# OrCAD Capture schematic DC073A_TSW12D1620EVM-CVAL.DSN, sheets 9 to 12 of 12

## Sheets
9 PAGE09 - USB: size B
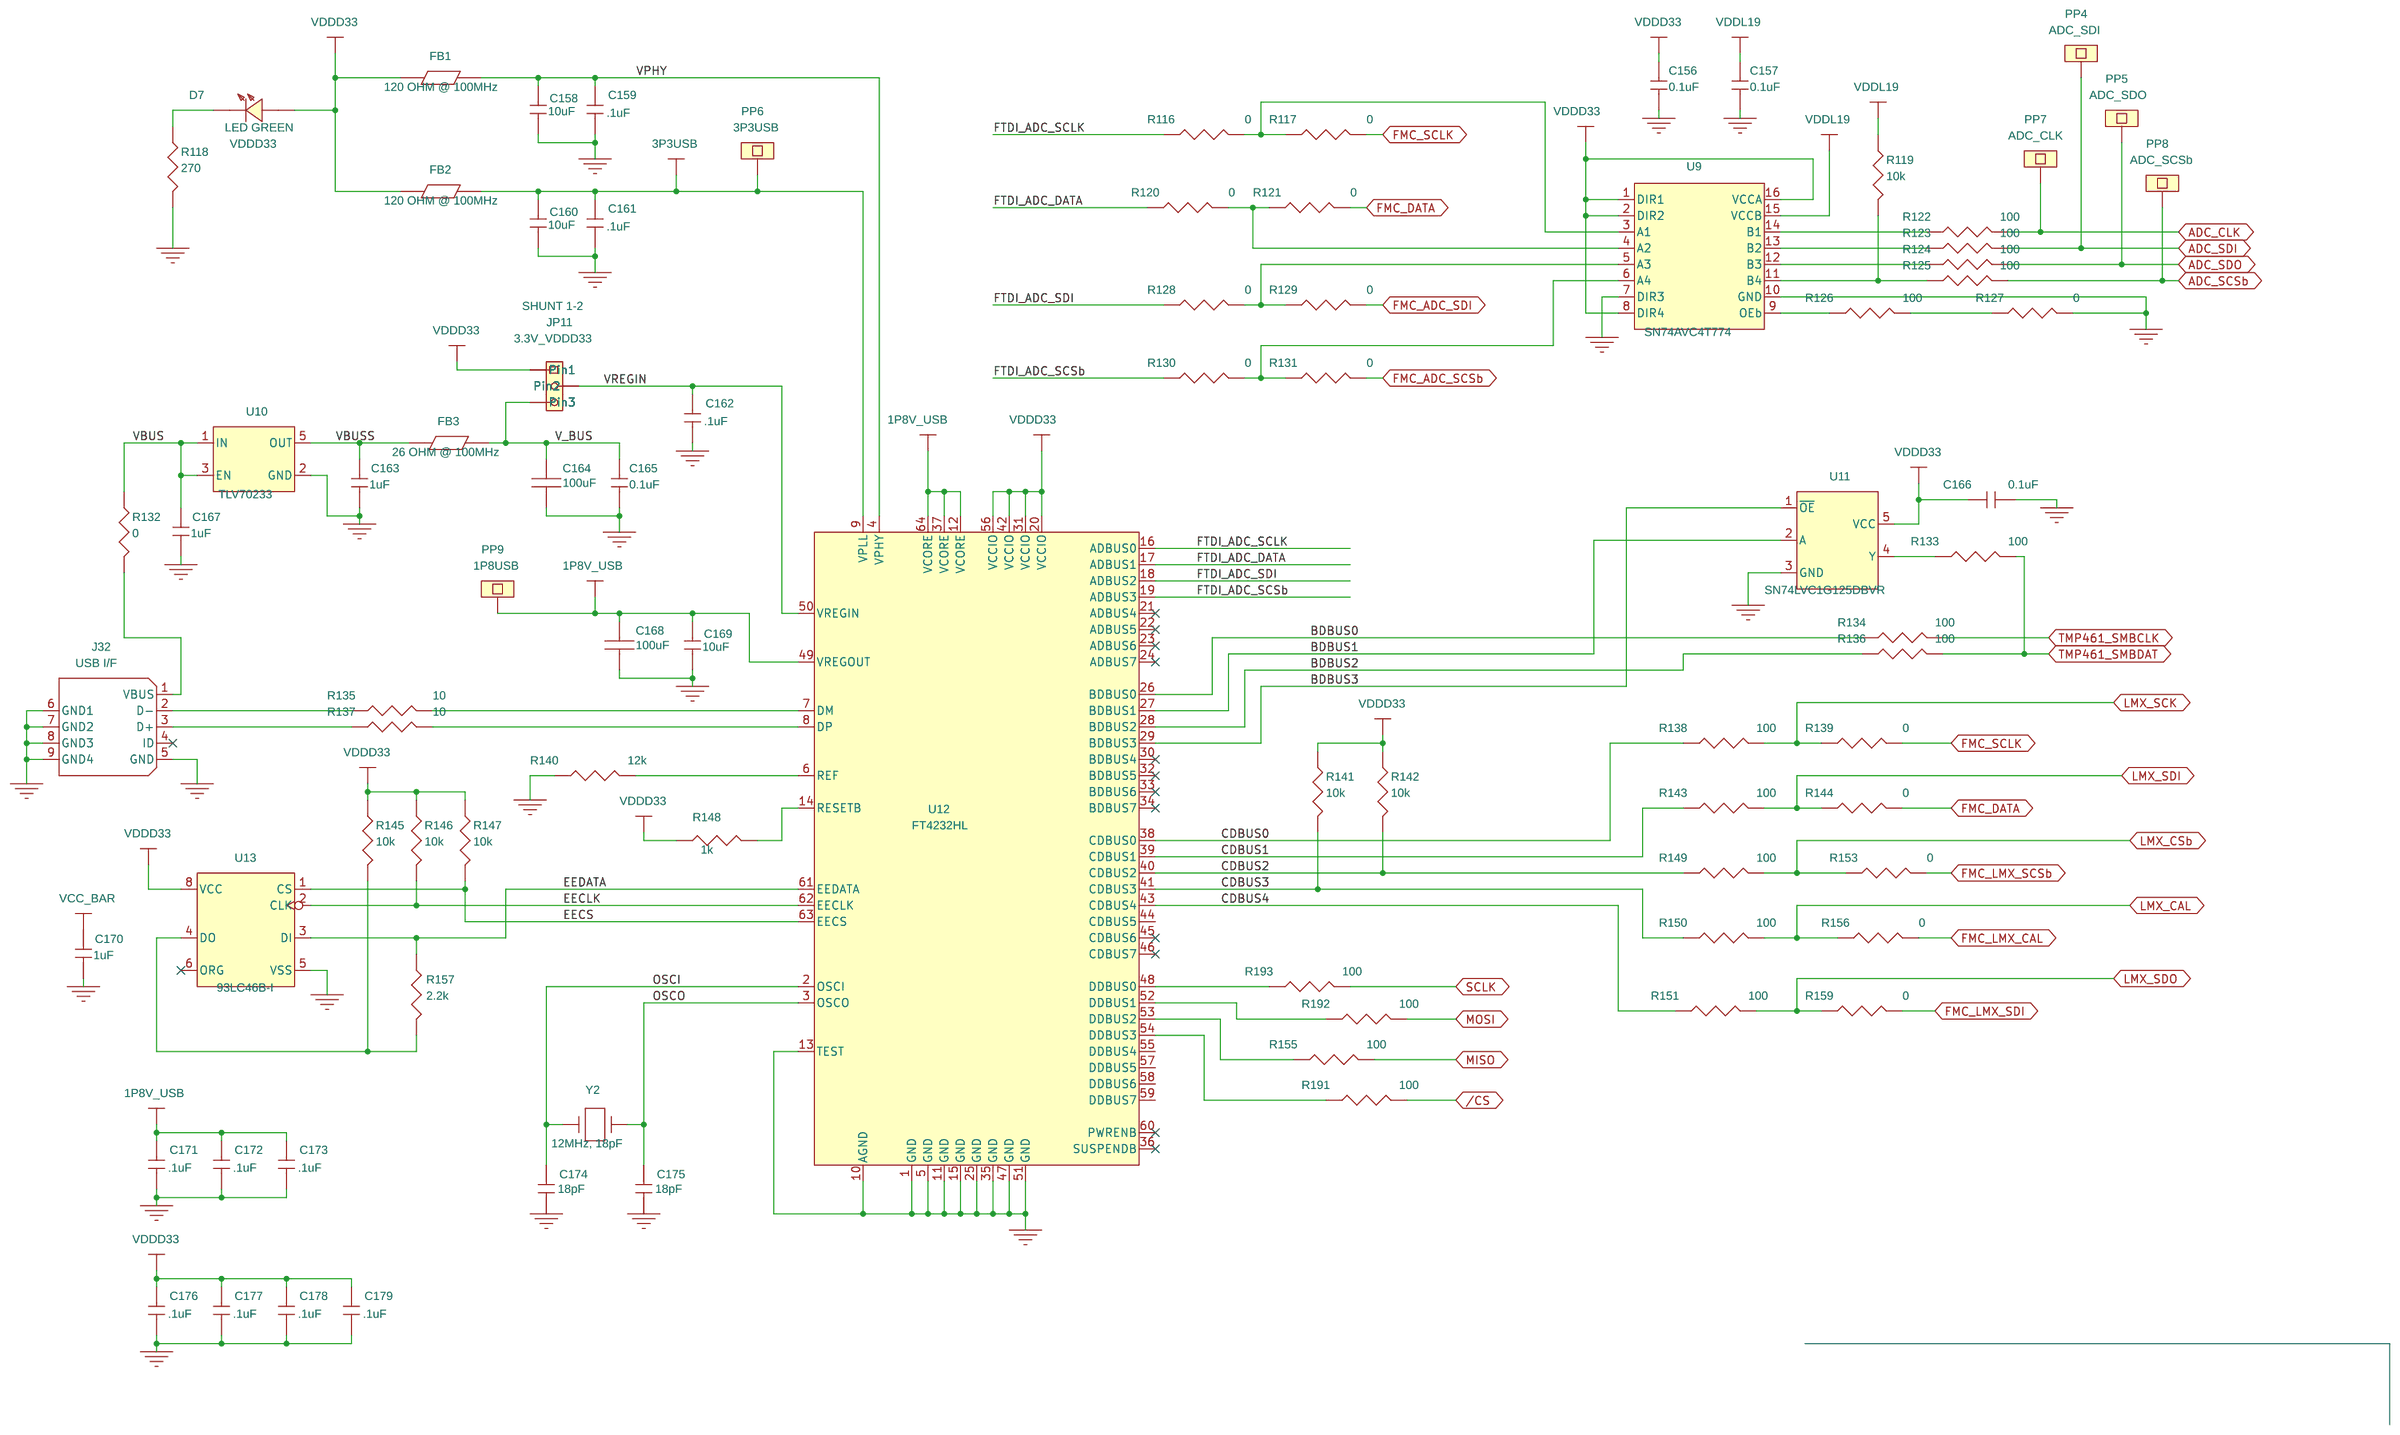
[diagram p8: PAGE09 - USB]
10 PAGE10 - POWER SUPPLIES: size B
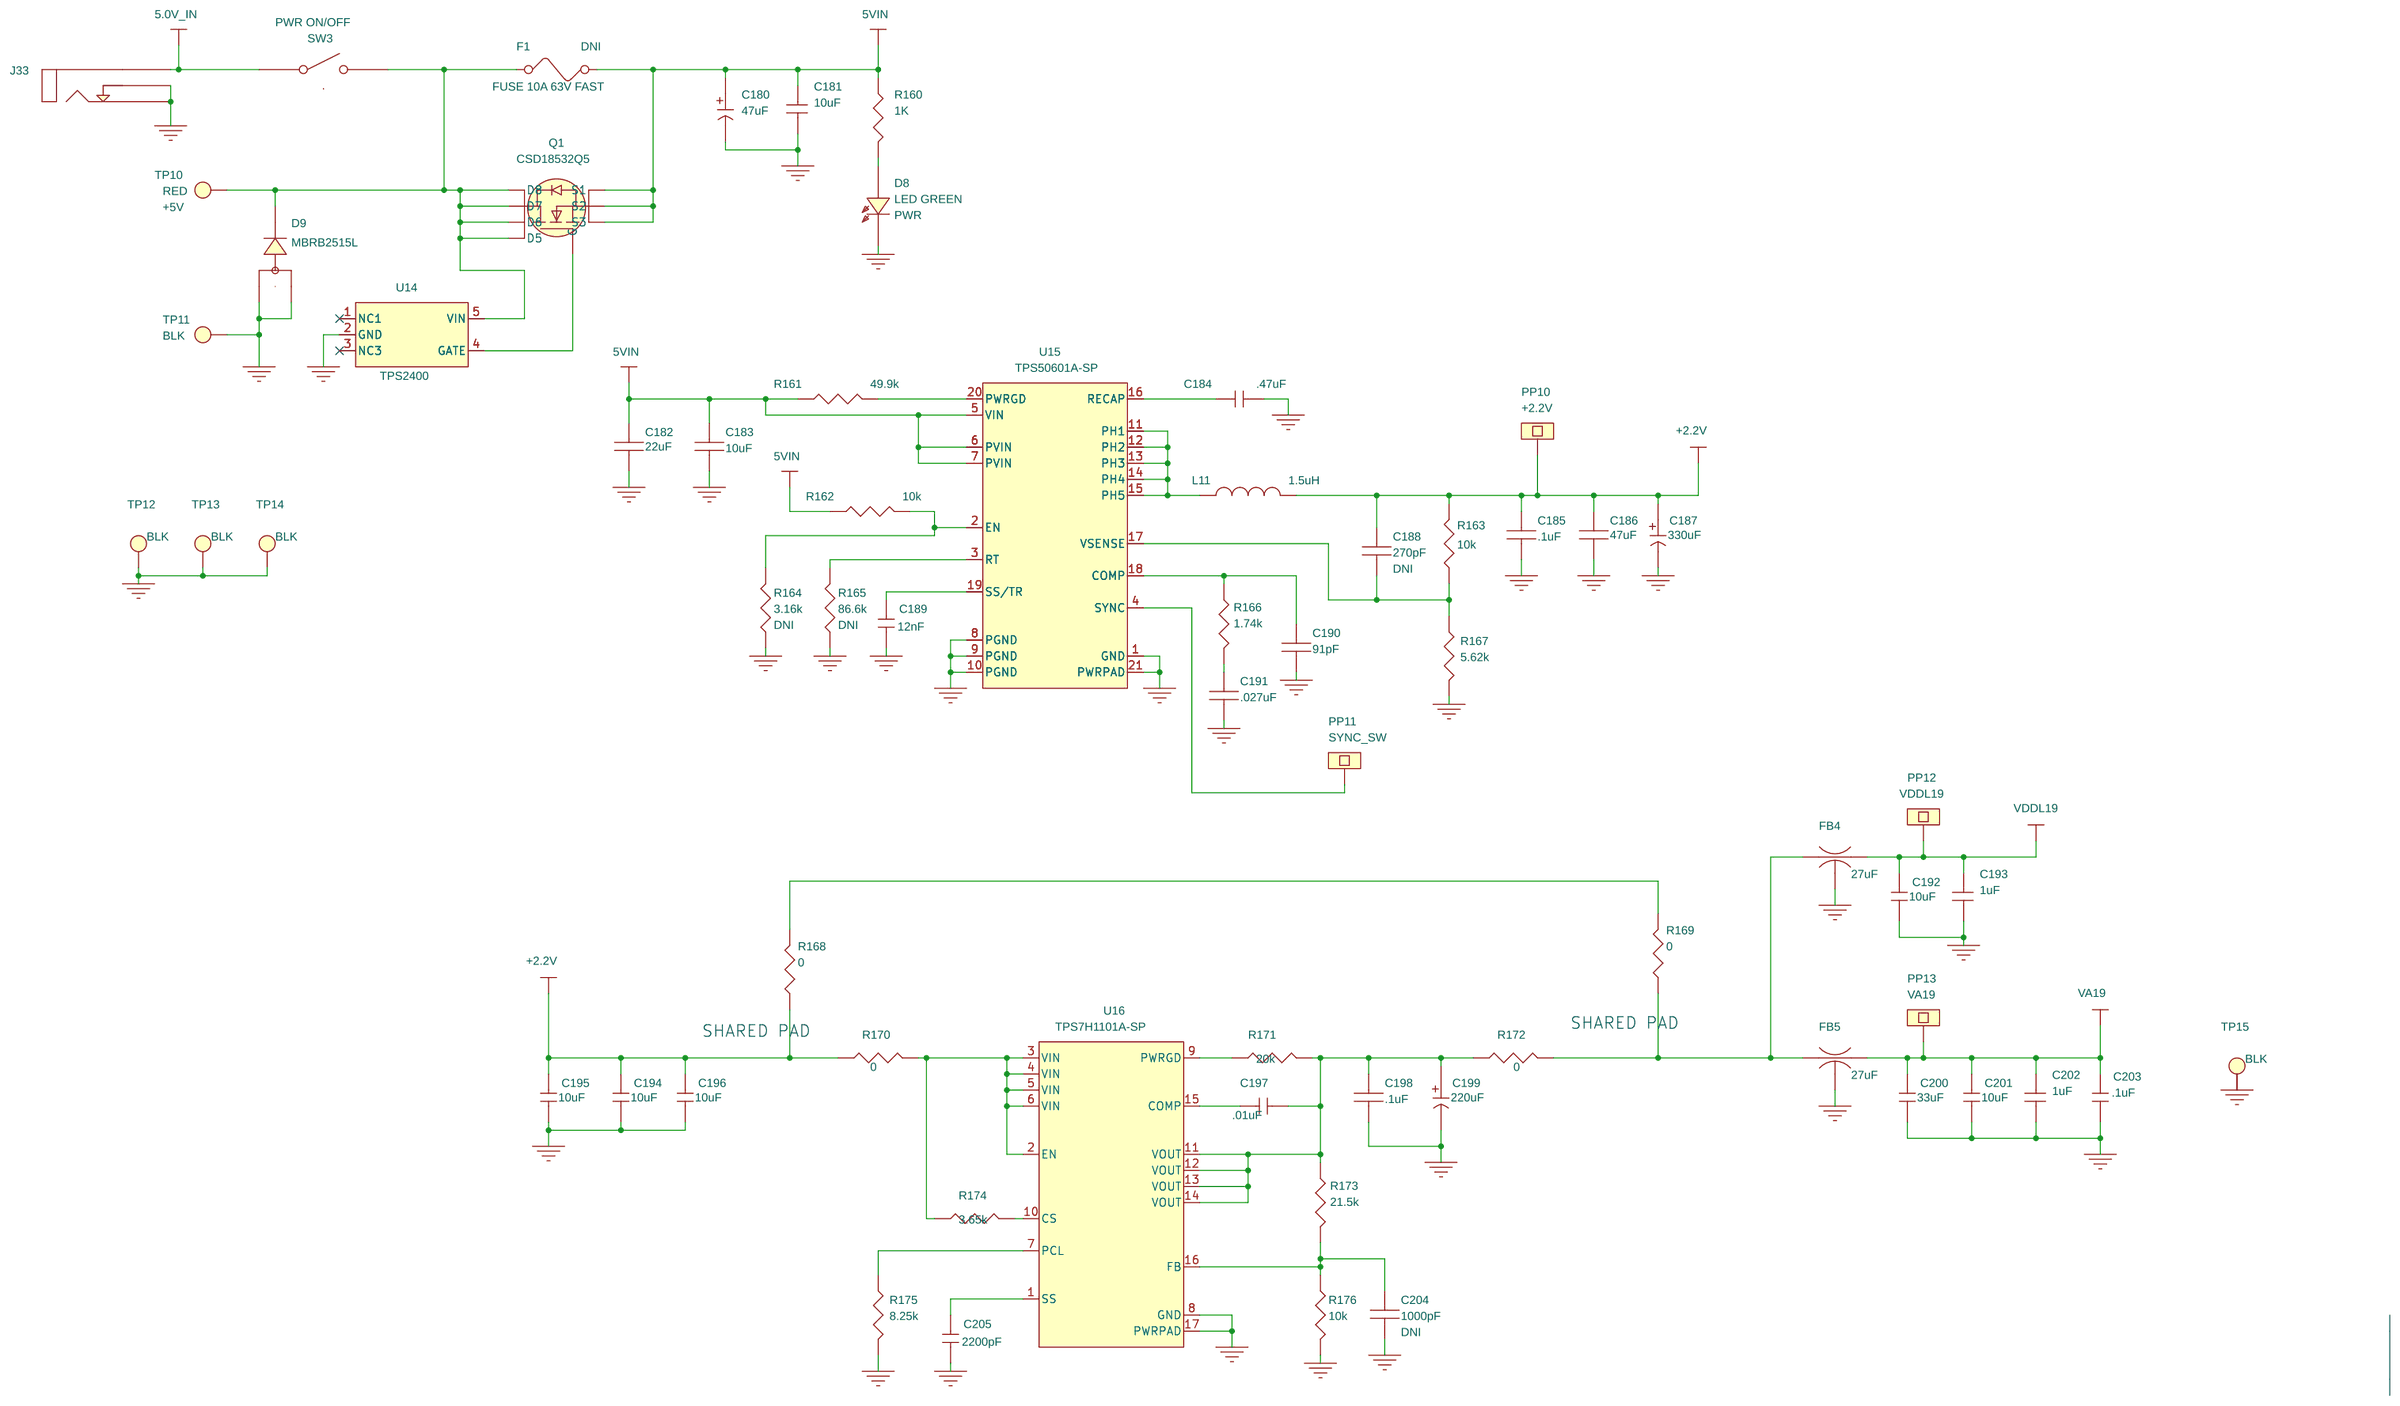
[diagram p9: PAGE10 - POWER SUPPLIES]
11 PAGE11 - POWER SUPPLIES: size B
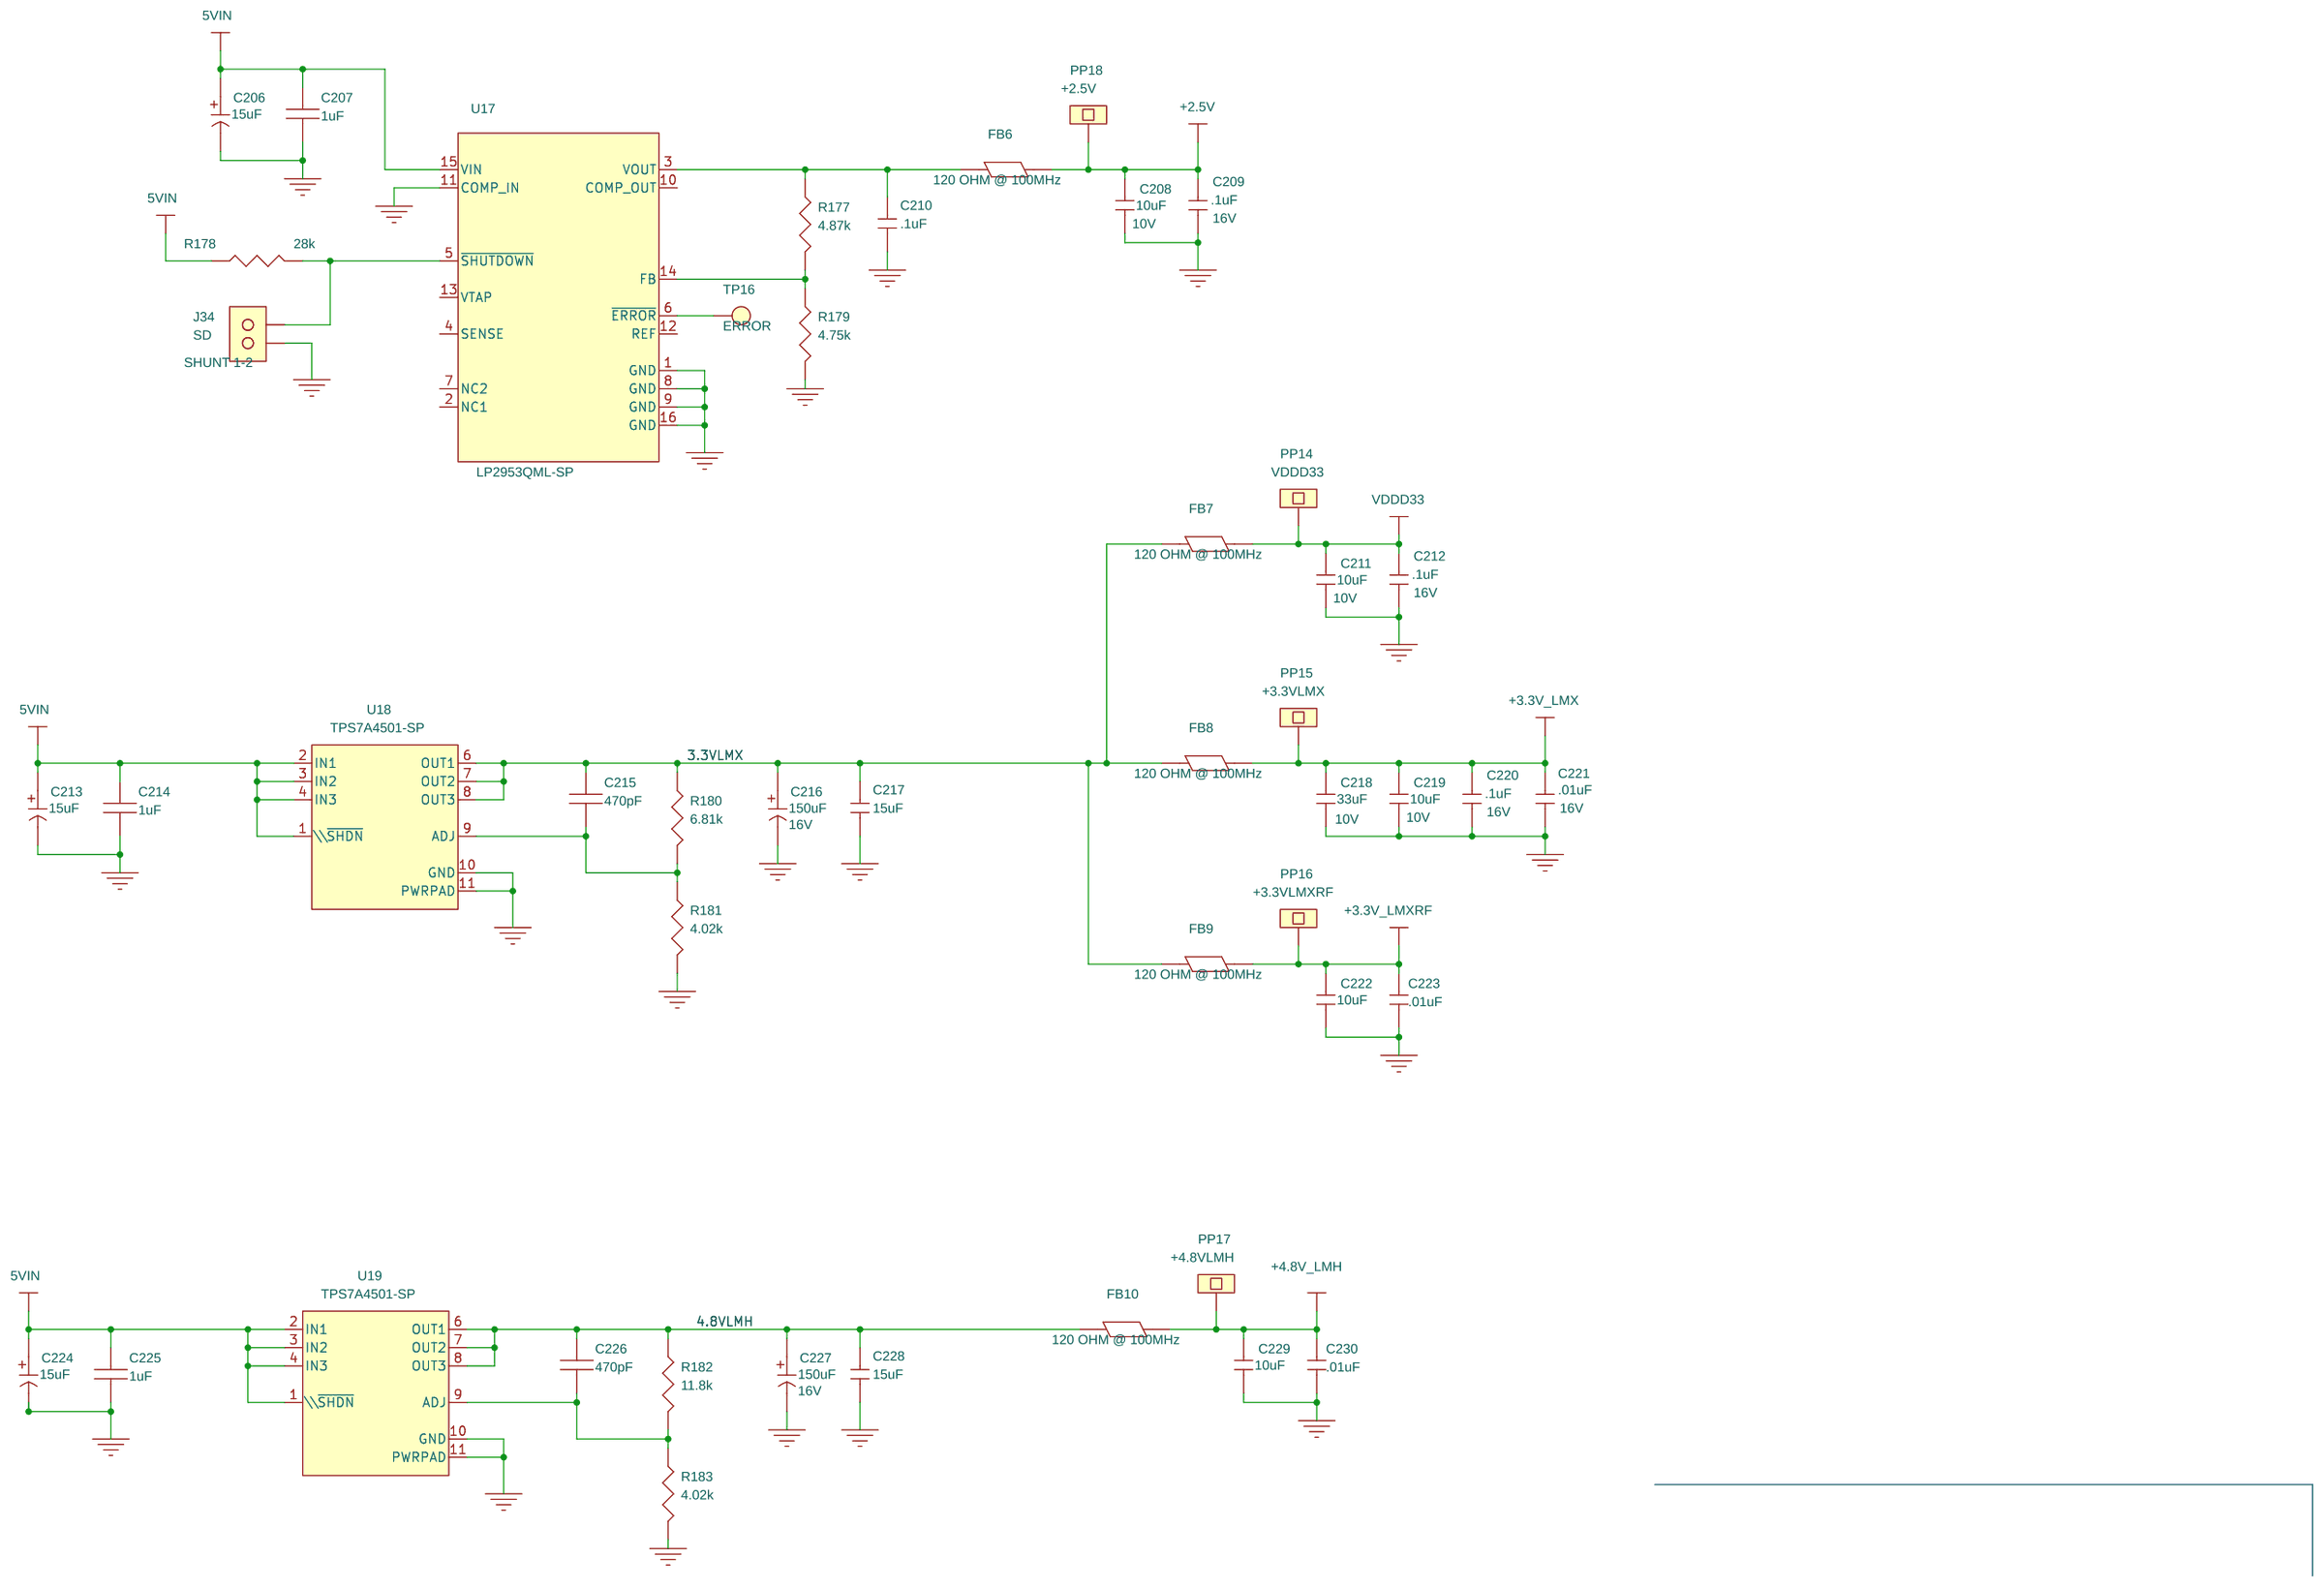
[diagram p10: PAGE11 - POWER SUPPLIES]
12 PAGE12 - MECHANICAL: size B
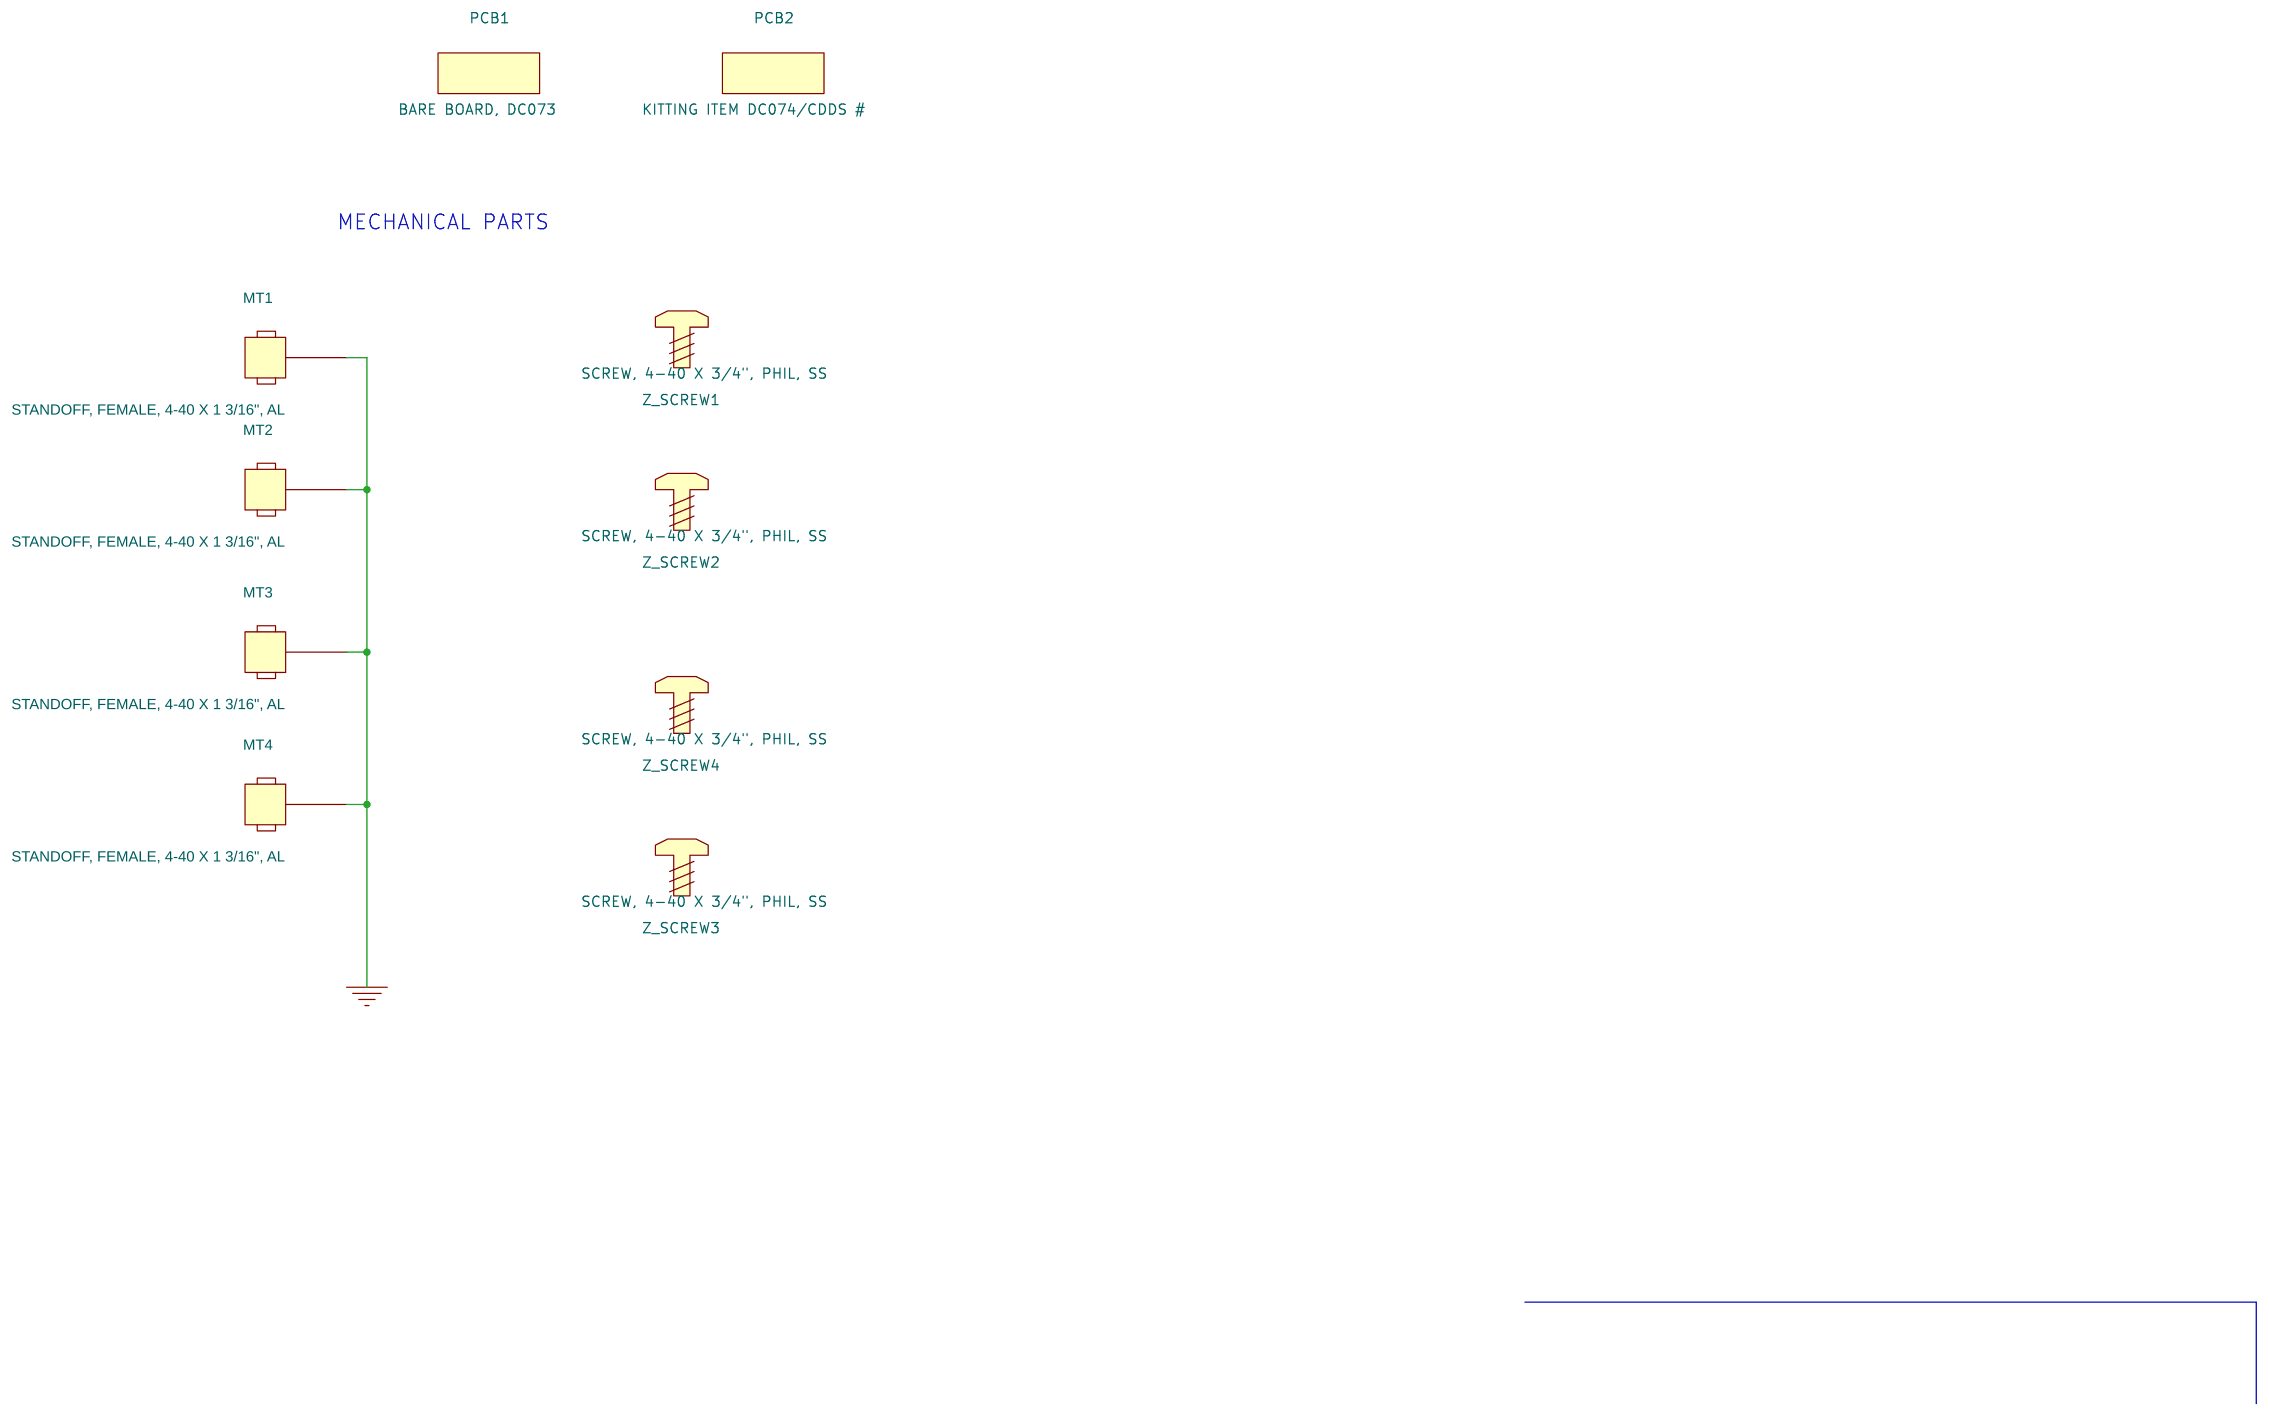
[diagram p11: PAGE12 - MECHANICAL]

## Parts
sheet PAGE09 - USB
C156  0.1uF  [0603]
C157  0.1uF  [0603]
C158  10uF  [0603]
C159  .1uF  [0201]
C160  10uF  [0603]
C161  .1uF  [0201]
C162  .1uF  [0201]
C163  1uF  [0603]
C164  100uF  [1206]
C165  0.1uF  [0603]
C166  0.1uF  [0603]
C167  1uF  [0603]
C168  100uF  [1206]
C169  10uF  [0603]
C170  1uF  [0603]
C171  .1uF  [0201]
C172  .1uF  [0201]
C173  .1uF  [0201]
C174  18pF  [0402]
C175  18pF  [0402]
C176  .1uF  [0201]
C177  .1uF  [0201]
C178  .1uF  [0201]
C179  .1uF  [0201]
D7  LED GREEN  [LED_0805]
FB1  120 OHM @ 100MHz  [IND_0603]
FB2  120 OHM @ 100MHz  [IND_0603]
FB3  26 OHM @ 100MHz  [IND_0603]
J32  CON, USB, MINI, AB, SMT  [CON_SMRT_USBMNE20_F]
JP11  HDR, THVT, 3POS, .100, GOLD  [HDR_THVT_1x3_100_M]
PP4  PROBE POINT  [PROBE_POINT_30PAD]
PP5  PROBE POINT  [PROBE_POINT_30PAD]
PP6  PROBE POINT  [PROBE_POINT_30PAD]
PP7  PROBE POINT  [PROBE_POINT_30PAD]
PP8  PROBE POINT  [PROBE_POINT_30PAD]
PP9  PROBE POINT  [PROBE_POINT_30PAD]
R116  0  [0402]
R117  0  [0402]
R118  270  [0402]
R119  10k  [0402]
R120  0  [0402]
R121  0  [0402]
R122  100  [0402]
R123  100  [0402]
R124  100  [0402]
R125  100  [0402]
R126  100  [0402]
R127  0  [0402]
R128  0  [0402]
R129  0  [0402]
R130  0  [0402]
R131  0  [0402]
R132  0  [0603]
R133  100  [0402]
R134  100  [0402]
R135  10  [0603]
R136  100  [0402]
R137  10  [0603]
R138  100  [0402]
R139  0  [0402]
R140  12k  [0603]
R141  10k  [0402]
R142  10k  [0402]
R143  100  [0402]
R144  0  [0402]
R145  10k  [0402]
R146  10k  [0402]
R147  10k  [0402]
R148  1k  [0603]
R149  100  [0402]
R150  100  [0402]
R151  100  [0402]
R153  0  [0402]
R155  100  [0402]
R156  0  [0402]
R157  2.2k  [0402]
R159  0  [0402]
R191  100  [0402]
R192  100  [0402]
R193  100  [0402]
U9  SN74AVC4T774  [TSSOP_16_201x177_26]
U10  TLV70233  [SOT_5_120x69_37]
U11  SN74LVC1G125DBVR  [SOT_5_120x69_57]
U12  FT4232HL  [LQFP_64_402x402_20]
U13  93LC46B-I  [MSOP_8_118x118_0p65MM]
Y2  12MHz, 18pF  [XTAL_2_SM_126x197]
Z_SH-H1  SHUNT- HEADER
sheet PAGE10 - POWER SUPPLIES
C180  47uF  [TANT_B]
C181  10uF  [0603]
C182  22uF  [1206]
C183  10uF  [0805]
C184  .47uF  [0402]
C185  .1uF  [0805]
C186  47uF  [1206]
C187  330uF  [TANT_D]
C188  270pF  [0603]
C189  12nF  [0402]
C190  91pF  [0805]
C191  .027uF  [0805]
C192  10uF  [0603]
C193  1uF  [0402]
C194  10uF  [0603]
C195  10uF  [0603]
C196  10uF  [0603]
C197  .01uF  [0201]
C198  .1uF  [0805]
C199  220uF  [TANT_D]
C200  33uF  [0805]
C201  10uF  [0603]
C202  1uF  [0402]
C203  .1uF  [0402]
C204  1000pF  [0805]
C205  2200pF  [0201]
D8  LED GREEN  [LED_0805]
D9  MBRB2515L  [DIODE_MBRB2515L]
F1  FUSE 10A 63V FAST  [1206]
FB4  27uF  [1206_BEAD_NFM31P]
FB5  27uF  [1206_BEAD_NFM31P]
J33  CONN, JACK, PWR, MINI, R/A, TH  [CON_RAPC722_JACK_THVT_3]
L11  1.5uH  [IND_SM_6p7MMx6p7MM]
PP10  PROBE POINT  [PROBE_POINT_30PAD]
PP11  PROBE POINT  [PROBE_POINT_30PAD]
PP12  PROBE POINT  [PROBE_POINT_30PAD]
PP13  PROBE POINT  [PROBE_POINT_30PAD]
Q1  CSD18532Q5  [SON_Q5B_8]
R160  1K  [0402]
R161  49.9k  [0402]
R162  10k  [0402]
R163  10k  [0603]
R164  3.16k  [0402]
R165  86.6k  [0402]
R166  1.74k  [0402]
R167  5.62k  [0603]
R168  0  [0805]
R169  0  [0805]
R170  0  [0805]
R171  20k  [0402]
R172  0  [0805]
R173  21.5k  [0402]
R174  3.65k  [0402]
R175  8.25k  [0402]
R176  10k  [0402]
SW3  PWR ON/OFF  [SW_SMVT_SPST_ES02]
TP10  RED  [TP_THVT_125_RND_063D]
TP11  BLK  [TP_THVT_125_RND_063D]
TP12  BLK  [TP_THVT_100_RND]
TP13  BLK  [TP_THVT_100_RND]
TP14  BLK  [TP_THVT_100_RND]
TP15  BLK  [TP_THVT_100_RND]
U14  TPS2400  [DBV5]
U15  TPS50601A-SP  [CFP_20_300x510_50_PWRPAD]
U16  TPS7H1101A-SP  [DUAL_FLATPACK_TPS7H1101-SP]
sheet PAGE11 - POWER SUPPLIES
C206  15uF  [TANT_X]
C207  1uF  [0805]
C208  10uF  [0603]
C209  .1uF  [0402]
C210  .1uF  [1210]
C211  10uF  [0603]
C212  .1uF  [0402]
C213  15uF  [TANT_X]
C214  1uF  [0805]
C215  470pF  [0805]
C216  150uF  [7343]
C217  15uF  [0805]
C218  33uF  [0805]
C219  10uF  [0603]
C220  .1uF  [0402]
C221  .01uF  [0201]
C222  10uF  [0603]
C223  .01uF  [0201]
C224  15uF  [TANT_X]
C225  1uF  [0805]
C226  470pF  [0805]
C227  150uF  [7343]
C228  15uF  [0805]
C229  10uF  [0603]
C230  .01uF  [0201]
FB6  120 OHM @ 100MHz  [1206]
FB7  120 OHM @ 100MHz  [1206]
FB8  120 OHM @ 100MHz  [1206]
FB9  120 OHM @ 100MHz  [1206]
FB10  120 OHM @ 100MHz  [1206]
J34  HDR, THVT, 2POS, .100, GOLD  [HDR_THVT_1x2_100_M]
PP14  PROBE POINT  [PROBE_POINT_30PAD]
PP15  PROBE POINT  [PROBE_POINT_30PAD]
PP16  PROBE POINT  [PROBE_POINT_30PAD]
PP17  PROBE POINT  [PROBE_POINT_30PAD]
PP18  PROBE POINT  [PROBE_POINT_30PAD]
R177  4.87k  [0805]
R178  28k  [0402]
R179  4.75k  [0805]
R180  6.81k  [0805]
R181  4.02k  [0805]
R182  11.8k  [0805]
R183  4.02k  [0805]
SHN12  SHUNT HEADER
TP16  ORN  [TP_THVT_100_RND]
U17  LP2953QML-SP  [CFP_NAC_16_0P5mm]
U18  TPS7A4501-SP  [CFP_10_270x276_50_PWRPAD]
U19  TPS7A4501-SP  [CFP_10_270x276_50_PWRPAD]
sheet PAGE12 - MECHANICAL
MT1  STANDOFF, FEMALE, 4-40 X 1 3/16", AL  [MFG125_PLATED]
MT2  STANDOFF, FEMALE, 4-40 X 1 3/16", AL  [MFG125_PLATED]
MT3  STANDOFF, FEMALE, 4-40 X 1 3/16", AL  [MFG125_PLATED]
MT4  STANDOFF, FEMALE, 4-40 X 1 3/16", AL  [MFG125_PLATED]
PCB1  BARE BOARD, DC073
PCB2  KITTING ITEM DC074/CDDS #
Z_SCREW1  SCREW, 4-40 X 3/4", PHIL, SS
Z_SCREW2  SCREW, 4-40 X 3/4", PHIL, SS
Z_SCREW3  SCREW, 4-40 X 3/4", PHIL, SS
Z_SCREW4  SCREW, 4-40 X 3/4", PHIL, SS

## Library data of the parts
C156 C157 C165 C166 = CAP_0603_0.1uF
C158 C160 C169 = CAP_0603_10uF: CLASS: DISCRETE
C159 C161 C162 C171-C173 C176-C179 = CAP_0201_0.1uF: Mfr_Name: MURATA; Mfr_Part_Number: GRM033R61A104KE15D
C163 C167 C170 = CAP_0603_1uF
C164 C168 = CAP_1206_100uF_6.3V
C174 C175 = CAP_0402_18pF
D7 = LED_GREEN_0: TI_SILKTEXT: VDDD33
FB1 FB2 = FERRITE_BEAD_0603_120_H
FB3 = FERRITE_BEAD_0603_26_H
J32 = USB_MINI_AB_MNE20-5G5P10: Mfr_Name: WURTH ELEKTRONIK; Mfr_Part_Number: 651305142821; TI_SILKTEXT: USB I/F
JP11 = JUMPER_1X3_100: Mfr_Part_Number: HTSW-103-07-G-S; Note: SHUNT 1-2; TI_Silktext: 3.3V_VDDD33
PP4 = PROBE_POINT_0: Mfr_Name: HARWIN; Mfr_Part_Number: P1113SS3; TI_Silktext: ADC_SDI
PP5 = PROBE_POINT_0: Mfr_Name: HARWIN; Mfr_Part_Number: P1113SS3; TI_Silktext: ADC_SDO
PP6 = PROBE_POINT_0: Mfr_Name: HARWIN; Mfr_Part_Number: P1113SS3; TI_Silktext: 3P3USB
PP7 = PROBE_POINT_0: Mfr_Name: HARWIN; Mfr_Part_Number: P1113SS3; TI_Silktext: ADC_CLK
PP8 = PROBE_POINT_0: Mfr_Name: HARWIN; Mfr_Part_Number: P1113SS3; TI_Silktext: ADC_SCSb
PP9 = PROBE_POINT_0: Mfr_Name: HARWIN; Mfr_Part_Number: P1113SS3; TI_Silktext: 1P8USB
R116 R120 R127 R128 R130 = Res_0402_Zero_H
R117 R121 R129 R131 R139 R144 R153 R156 R159 = Res_0402_Zero_H_DNI: Mfr_Part_Number: ERJ-2GE0R00X
R118 = Res_0402_270
R119 R141 R142 R145-R147 R176 = Res_0402_10k
R122-R126 R133 R134 R136 R138 R143 R149-R151 R155 R191-R193 = Res_0603_100_H: Mfr_Part_Number: ERJ-2RKF1000X
R132 = Res_0603_Zero
R135 R137 = Res_0603_10
R140 = Res_0603_12k
R148 = Res_0603_1k_H
R157 = Res_0603_2.2k: Mfr_Part_Number: ERJ-2RKF2201X
U9 = SN74AVC4T774: Mfr_Name: Texas Instruments
U10 = TLV702: Mfr_Part_Number: TLV70233DBVT
U11 = SN74LVC1G125DBVR: Mfr_Name: Texas Instruments
U12 = FT4232HL: Mfr_Part_Number: FT4232HL-REEL
U13 = EEPROM_93LC46B: Mfr_Part_Number: 93LC46B-I/MS
Y2 = CRYSTAL_ABM3_0
Z_SH-H1 = SHUNT-HEADER_-_3POS: Mfr_Part_Number: 1-382811-6
C180 = CAP_POL-B_0: Mfr_Name: AVX; Mfr_Part_Number: TPSB476K010R0250; TOL: 10%
C181 = CAP_NP_1: Mfr_Name: TDK; Mfr_Part_Number: C1608X5R1A106K080AC; TOL: 10%; VOLTAGE: 10V
C182 = CAP_1206_2.2uF: Mfr_Part_Number: GRM31CR61A226ME19L
C183 = CAP_0805_10uF_10V: Mfr_Part_Number: GCJ21BR71A106KE01L
C184 = CAP_0805_0.1uF_X7R_50V: Mfr_Name: Taiyo Yuden; Mfr_Part_Number: LMK105BJ474KV-F
C185 C198 = CAP_0805_.1uF_25V
C186 = CAP_1206_47uF: Mfr_Part_Number: GRM31CE70G476ME15L
C187 = CAP_TANT_D_220uF_6.3V: Mfr_Name: KEMET; Mfr_Part_Number: T491D337K006AT; Tol: 10%
C188 = CAP_0805_9.0pF: Mfr_Name: Murata; Mfr_Part_Number: GCM1885C2A271FA16D; Note: DNI
C189 = CAP_0201_0.1uF: Mfr_Name: MURATA; Mfr_Part_Number: GRM155R71C123JA01D
C190 = CAP_0805_91pF_50V
C191 = CAP_0805_.027uF_50V
C192 C194-C196 C201 = CAP0201_0: Mfr_Name: TDK; Mfr_Part_Number: C1608X5R1A106K080AC; TOL: 20%; VOLTAGE: 10V
C193 C202 = CAP_NP_1: Mfr_Name: YAGEO; Mfr_Part_Number: CC0402MRX5R6BB105; TOL: 20%; VOLTAGE: 6.3V
C197 = CAP_0201_10000pF
C199 = CAP_TANT_D_220uF_6.3V
C200 C218 = CAP0201_0: Mfr_Name: TDK; Mfr_Part_Number: C2012X5R1A336M125AC; TOL: 20%; VOLTAGE: 10V
C203 C209 C212 C220 = CAP0603: Mfr_Name: MURATA; Mfr_Part_Number: GRM155R71C104KA88D; TOL: 10%; Voltage: 16V
C204 = CAP_0805_1000pF_25V: Mfr_Part_Number: GRM216R71E102KA01D; Note: DNI
C205 = CAP_0201_2200pF
D8 = LED_GREEN_0: Mfr_Part_Number: LTST-C170KGKT; TI_SILKTEXT: PWR
D9 = DIODE_MBRB2515L
F1 = FUSE_0: Mfr_Name: TE Connectivity; Mfr_Part_Number: 1206SFF200F/63-2; Note: DNI
FB4 FB5 = BEAD_NFM31P: Mfr_Name: Murata; Mfr_Part_Number: NFM31PC276B0J3L; Tolerance: 20%
J33 = CONN_JACK_PWR: Mfr_Name: SWITCHCRAFT; Mfr_Part_Number: RAPC722X
L11 = IND_POWER_1.5uH
PP10 = PROBE_POINT_0: Mfr_Name: HARWIN; Mfr_Part_Number: P1113SS3; TI_Silktext: +2.2V
PP11 = PROBE_POINT_0: Mfr_Name: HARWIN; Mfr_Part_Number: P1113SS3; TI_Silktext: SYNC_SW
PP12 = PROBE_POINT_0: Mfr_Name: HARWIN; Mfr_Part_Number: P1113SS3; TI_Silktext: VDDL19
PP13 = PROBE_POINT_0: Mfr_Name: HARWIN; Mfr_Part_Number: P1113SS3; TI_Silktext: VA19
Q1 = CSD18532Q5B: Mfr_Name: Texas Instruments
R160 = Res_0402_1k: TOL: 1%
R161 = Res_0402_49.9k: Mfr_Part_Number: ERJ-2RKF4992X
R162 = Res_0402_28k_H: Mfr_Part_Number: ERJ-2RKF1002X
R163 = Res_0402_10k_H: Mfr_Part_Number: ERJ-3EKF1002V
R164 = Res_0402_9.31k_H: Mfr_Part_Number: ERJ-2RKF3161X; Note: DNI
R165 = Res_0402_86.6k_H: Mfr_Part_Number: ERJ-2RKF8662X; Note: DNI
R166 = Res_0402_1.82k: Mfr_Part_Number: ERJ-2RKF1741X
R167 = Res_0805_4.87k: ALTERNATE_PART_NUMBER: 7.15k, ERJ-6ENF7151V; Mfr_Name: PANASONIC; Mfr_Part_Number: ERJ-3EKF5621V
R168-R170 R172 = Res_0402_Zero_H_DNI: Mfr_Name: Keystone; Mfr_Part_Number: 5106
R171 = Res_0402_20K_H
R173 = Res_0402_21.5k
R174 = Res_0402_3.65K_H
R175 = Res_0402_8.25: Mfr_Part_Number: CRCW04028K25FKED
SW3 = SW_KEY-SPST_1: Mfr_Name: C&K; Mfr_Part_Number: ES02MSABE
TP10 = TESTLOOP_BLACK: Mfr_Name: KEYSTONE; Mfr_Part_Number: 5010; TI_SILKTEXT: +5V
TP11 = TESTPOINT_BLK: Mfr_Name: KEYSTONE; Mfr_Part_Number: 5011
TP12-TP15 = TESTPOINT_BLK: Mfr_Name: KEYSTONE; Mfr_Part_Number: 5001
U14 = TPS2400: Mfr_Name: Texas Instruments; Mfr_Part_Number: TPS2400DBVT
U15 = TPS50601A-SP_0
U16 = TPS7H1101-SP: Mfr_Part_Number: TPS7H1101AHKR/EM
C206 C213 C224 = CAP_TANT_X_15uF_50V
C207 C214 C225 = CAP_0805_1uF_50V
C208 C211 C219 C222 C229 = CAP0201_0: Mfr_Name: TDK; Mfr_Part_Number: C1608X5R1A106K080AC; TOL: 10%; VOLTAGE: 10V
C210 = CAP_1210_.1uF_50V
C215 C226 = CAP_0805_470pF
C216 C227 = CAP_TANT_X_15uF_50V: Mfr_Name: AVX; Mfr_Part_Number: TPME157K016R0030; Tol: 10%; Voltage: 16V
C217 C228 = CAP_1210_.1uF_50V: Mfr_Name: TDK; Mfr_Part_Number: C2012X5R1C156M125AC
C221 C223 C230 = CAP0402_0: Mfr_Name: YAGEO; Mfr_Part_Number: CC0201KRX7R7BB103; TOL: 10%; Voltage: 16V
FB6-FB10 = FERRITE_BEAD_0402_H: Isat: 500mA; Mfr_Name: MURATA; Mfr_Part_Number: BLM31PG121SN1L
J34 = HEADER_1x2_0: Mfr_Part_Number: HTSW-102-07-G-S; Note: SHUNT 1-2; TI_SILKTEXT: SD
PP14 = PROBE_POINT_0: Mfr_Name: HARWIN; Mfr_Part_Number: P1113SS3; TI_Silktext: VDDD33
PP15 = PROBE_POINT_0: Mfr_Name: HARWIN; Mfr_Part_Number: P1113SS3; TI_Silktext: +3.3VLMX
PP16 = PROBE_POINT_0: Mfr_Name: HARWIN; Mfr_Part_Number: P1113SS3; TI_Silktext: +3.3VLMXRF
PP17 = PROBE_POINT_0: Mfr_Name: HARWIN; Mfr_Part_Number: P1113SS3; TI_Silktext: +4.8VLMH
PP18 = PROBE_POINT_0: Mfr_Name: HARWIN; Mfr_Part_Number: P1113SS3; TI_Silktext: +2.5V
R177 = Res_0805_6.81k: Mfr_Part_Number: ERJ-6ENF4871V
R178 = Res_0402_28k_H
R179 = Res_0805_4.02k: Mfr_Part_Number: ERJ-6ENF4751V
R180 = Res_0805_6.81k
R181 R183 = Res_0805_4.02k
R182 = Res_0805_6.81k: Mfr_Part_Number: ERJ-6ENF1182V
SHN12 = SHUNT_HEADER: Mfr_Name: Sullins; Mfr_Part_Number: SPC02SYAN
TP16 = TESTPOINT_ORANGE: TI_SILKTEXT: ERROR
U17 = LP2953QML-SP
U18 U19 = TPS7A4501-SP
MT1-MT4 = MOUNTING_HOLE: Mfr_Name: RAF; Mfr_Part_Number: 1648-440-AL
PCB1 = BARE_BOARD: Mfr_Name: ANY VENDOR; Mfr_Part_Number: TSW12D1620EVM-CVAL REV A
PCB2 = BARE_BOARD: Mfr_Name: ANY VENDOR; Mfr_Part_Number: DC074 REV A
Z_SCREW1-Z_SCREW4 = STANDOFF-SCREW: Mfr_Part_Number: PMSSS 440 0075 PH; Note: SCREW FOR STANDOFF

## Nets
3.3VLMX: C215.1 C216.1 C217.1 FB7.1 FB8.1 FB9.1 R180.1 U18.6(OUT1) U18.7(OUT2) U18.8(OUT3)
4.8VLMH: C226.1 C227.1 C228.1 FB10.1 R182.1 U19.6(OUT1) U19.7(OUT2) U19.8(OUT3)
5.0V_IN: J33.1 SW3.1
5VIN: C180.1 C181.1 C182.1 C183.1 C206.1 C207.1 C213.1 C214.1 C224.1 C225.1 F1.2 Q1.1(S1) Q1.2(S2) Q1.3(S3) R160.1 R161.1 R162.1 R178.1 U15.5(VIN) U15.6(PVIN) U15.7(PVIN) U17.15(VIN) U18.1(\\~{SHDN}) U18.2(IN1) U18.3(IN2) U18.4(IN3) U19.1(\\~{SHDN}) U19.2(IN1) U19.3(IN2) U19.4(IN3)
+2.2V: C185.1 C186.1 C187.1 C188.1 C194.1 C195.1 C196.1 L11.2 PP10.1 R163.2 R168.1 R170.1
+2.5V: C208.1 C209.1 FB6.2 PP18.1 ; also on sheet 5
+3.3V_LMX: C218.1 C219.1 C220.1 C221.1 FB8.2 PP15.1 ; also on sheet 7
+3.3V_LMXRF: C222.1 C223.1 FB9.2 PP16.1 ; also on sheet 7
+4.8V_LMH: C229.1 C230.1 FB10.2 PP17.1 ; also on sheet 3
GND: C156.2 C157.2 C158.2 C159.2 C160.2 C161.2 C162.2 C163.2 C164.2 C165.2 C166.2 C167.2 C168.2 C169.2 C170.2 C171.2 C172.2 C173.2 C174.2 C175.2 C176.2 C177.2 C178.2 C179.2 C180.2 C181.2 C182.2 C183.2 C184.2 C185.2 C186.2 C187.2 C189.2 C190.2 C191.2 C192.2 C193.2 C194.2 C195.2 C196.2 C198.2 C199.2 C200.2 C201.2 C202.2 C203.2 C204.2 C205.2 C206.2 C207.2 C208.2 C209.2 C210.2 C211.2 C212.2 C213.2 C214.2 C216.2 C217.2 C218.2 C219.2 C220.2 C221.2 C222.2 C223.2 C224.2 C225.2 C227.2 C228.2 C229.2 C230.2 D8.2(CATHODE) D9.1 D9.3 FB4.2 FB5.2 J32.5(GND) J32.6(GND1) J32.7(GND2) J32.8(GND3) J32.9(GND4) J33.2 J33.3 J34.2 MT1.1 MT2.1 MT3.1 MT4.1 R118.2 R127.2 R140.1 R164.1 R165.1 R167.2 R175.2 R176.2 R179.2 R181.2 R183.2 TP11.1(TP) TP12.1(TP) TP13.1(TP) TP14.1(TP) TP15.1(TP) U9.7(DIR3) U9.10(GND) U10.2(GND) U11.3(GND) U12.1(GND) U12.5(GND) U12.10(AGND) U12.11(GND) U12.13(TEST) U12.15(GND) U12.25(GND) U12.35(GND) U12.47(GND) U12.51(GND) U13.5(VSS) U14.2(GND) U15.1(GND) U15.8(PGND) U15.9(PGND) U15.10(PGND) U15.21(PWRPAD) U16.8(GND) U16.17(PWRPAD) U17.1(GND) U17.8(GND) U17.9(GND) U17.11(COMP_IN) U17.16(GND) U18.10(GND) U18.11(PWRPAD) U19.10(GND) U19.11(PWRPAD) ; also on sheet 1 3 4 5 6 7 8
VBUS: C167.1 R132.1 U10.1(IN) U10.3(EN)
VBUSS: C163.1 FB3.1 U10.5(OUT)
VDDD33: C156.1 C166.1 C170.1 C176.1 C177.1 C178.1 C179.1 C211.1 C212.1 D7.1(ANODE) FB1.1 FB2.1 FB7.2 JP11.1(Pin1) PP14.1 R141.1 R142.1 R145.1 R146.1 R147.1 R148.1 U9.1(DIR1) U9.2(DIR2) U9.8(DIR4) U9.16(VCCA) U11.5(VCC) U12.20(VCCIO) U12.31(VCCIO) U12.42(VCCIO) U12.56(VCCIO) U13.8(VCC) ; also on sheet 1 4
VDDL19: C157.1 C192.1 C193.1 FB4.3 PP12.1 R119.1 U9.15(VCCB) ; also on sheet 4
1P8V_USB: C168.1 C169.1 C171.1 C172.1 C173.1 PP9.1 U12.12(VCORE) U12.37(VCORE) U12.49(VREGOUT) U12.64(VCORE)
2: D9.2
3P3USB: C160.1 C161.1 FB2.2 PP6.1 U12.9(VPLL)
/CS: R191.2 ; also on sheet 1
ADC_CLK: PP7.1 R122.2 ; also on sheet 4
ADC_SCSb: PP8.1 R125.2 ; also on sheet 4
ADC_SDI: PP4.1 R123.2 ; also on sheet 4
ADC_SDO: PP5.1 R124.2 ; also on sheet 4
BDBUS0: R134.1 U12.26(BDBUS0)
BDBUS1: U11.2(A) U12.27(BDBUS1)
BDBUS2: R136.1 U12.28(BDBUS2)
BDBUS3: U11.1(~{OE}) U12.29(BDBUS3)
CDBUS0: R138.1 U12.38(CDBUS0)
CDBUS1: R143.1 U12.39(CDBUS1)
CDBUS2: R142.2 R149.1 U12.40(CDBUS2)
CDBUS3: R141.2 R150.1 U12.41(CDBUS3)
CDBUS4: R151.1 U12.43(CDBUS4)
EECLK: R146.2 U12.62(EECLK) U13.2(CLK)
EECS: R147.2 U12.63(EECS) U13.1(CS)
EEDATA: R157.1 U12.61(EEDATA) U13.3(DI)
FMC_ADC_SCSb: R131.2 ; also on sheet 8
FMC_ADC_SDI: R129.2 ; also on sheet 8
FMC_DATA: R121.2 R144.2 ; also on sheet 8
FMC_LMX_CAL: R156.2 ; also on sheet 8
FMC_LMX_SCSb: R153.2 ; also on sheet 8
FMC_LMX_SDI: R159.2 ; also on sheet 8
FMC_SCLK: R117.2 R139.2 ; also on sheet 8
FTDI_ADC_DATA: R120.1 U12.17(ADBUS1)
FTDI_ADC_SCLK: R116.1 U12.16(ADBUS0)
FTDI_ADC_SCSb: R130.1 U12.19(ADBUS3)
FTDI_ADC_SDI: R128.1 U12.18(ADBUS2)
LMX_CAL: R150.2 R156.1 ; also on sheet 7
LMX_CSB: R149.2 R153.1 ; also on sheet 7
LMX_SCK: R138.2 R139.1 ; also on sheet 7
LMX_SDI: R143.2 R144.1 ; also on sheet 7
LMX_SDO: R151.2 R159.1 ; also on sheet 7
MISO: R155.2 ; also on sheet 1
MOSI: R192.2 ; also on sheet 1
OSCI: C174.1 U12.2(OSCI) Y2.2
OSCO: C175.1 U12.3(OSCO) Y2.1
SCLK: R193.2 ; also on sheet 1
TMP461_SMBCLK: R134.2 ; also on sheet 4
TMP461_SMBDAT: R133.2 R136.2 ; also on sheet 4
V_BUS: C164.1 C165.1 FB3.2 JP11.3(Pin3)
VA19: C200.1 C201.1 C202.1 C203.1 FB5.3 PP13.1 ; also on sheet 6
VPHY: C158.1 C159.1 FB1.2 U12.4(VPHY)
VREGIN: C162.1 JP11.2(Pin2) U12.50(VREGIN)
N18123409: D9.4 F1.1 Q1.5(D5) Q1.6(D6) Q1.7(D7) Q1.8(D8) SW3.3 TP10.1(TP) U14.5(VIN)
N18340257: D8.1(ANODE) R160.2
N19955835: Q1.4(G) U14.4(GATE)
N20760406: C215.2 R180.2 R181.1 U18.9(ADJ)
N20772111: C188.2 R163.1 R167.1 U15.17(VSENSE)
N20772147: C191.1 R166.2
N20772149: C190.1 R166.1 U15.18(COMP)
N20772252: R161.2 U15.20(PWRGD)
N20772286: R162.2 R164.2 U15.2(EN)
N20772300: R165.2 U15.3(RT)
N20772322: C189.1 U15.19(SS/TR)
N20772348: C184.1 U15.16(RECAP)
N20772352: L11.1 U15.11(PH1) U15.12(PH2) U15.13(PH3) U15.14(PH4) U15.15(PH5)
N20774965: R170.2 R174.1 U16.2(EN) U16.3(VIN) U16.4(VIN) U16.5(VIN) U16.6(VIN)
N20775006: C205.1 U16.1(SS)
N20775018: C197.1 U16.15(COMP)
N20775020: C197.2 C198.1 C199.1 R171.2 R172.1 R173.1 U16.11(VOUT) U16.12(VOUT) U16.13(VOUT) U16.14(VOUT)
N20775032: R171.1 U16.9(PWRGD)
N20775050: R175.1 U16.7(PCL)
N20775064: R174.2 U16.10(CS)
N20775144: C204.1 R173.2 R176.1 U16.16(FB)
N20776453: FB4.1 FB5.1 R169.1 R172.2
N20810898: PP11.1 U15.4(SYNC)
N21127493: R133.1 U11.4(Y)
N21129355: D7.2(CATHODE) R118.1
N21131028: R148.2 U12.14(RESETB)
N21131030: R140.2 U12.6(REF)
N21131895: R145.2 R157.2 U13.4(DO)
N21135480: J32.1(VBUS) R132.2
N21135675: J32.3(D+) R137.1
N21135677: J32.2(D-) R135.1
N21135903: R135.2 U12.7(DM)
N21135906: R137.2 U12.8(DP)
N21306634: C226.2 R182.2 R183.1 U19.9(ADJ)
N21435177: R168.2 R169.2
N21453692: C210.1 FB6.1 R177.1 U17.3(VOUT)
N21453823: R177.2 R179.1 U17.14(FB)
N21482374: J34.1 R178.2 U17.5(~{SHUTDOWN})
N21491465: R130.2 R131.1 U9.6(A4)
N21491508: R128.2 R129.1 U9.5(A3)
N21491543: R120.2 R121.1 U9.4(A2)
N21491580: R116.2 R117.1 U9.3(A1)
N21491663: R126.2 R127.1
N21491825: R122.1 U9.14(B1)
N21491829: R123.1 U9.13(B2)
N21491833: R124.1 U9.12(B3)
N21491837: R119.2 R125.1 U9.11(B4)
N21491881: R126.1 U9.9(OEb)
N21594563: TP16.1(TP) U17.6(~{ERROR})
N21623803: R192.1 U12.52(DDBUS1)
N21623805: R191.1 U12.54(DDBUS3)
N21623807: R193.1 U12.48(DDBUS0)
N21623845: R155.1 U12.53(DDBUS2)
N21672893: SW3.2 SW3.4 SW3.5

Not connected (* = marked no-connect by the designer): J32 4(ID)*; U12 21(ADBUS4)* 22(ADBUS5)* 23(ADBUS6)* 24(ADBUS7)* 30(BDBUS4)* 32(BDBUS5)* 33(BDBUS6)* 34(BDBUS7)* 36(SUSPENDB)* 44(CDBUS5) 45(CDBUS6)* 46(CDBUS7)* 55(DDBUS4) 57(DDBUS5) 58(DDBUS6) 59(DDBUS7) 60(PWRENB)*; U13 6(ORG)*; U14 1(NC1)* 3(NC3)*; U17 2(NC1) 4(SENSE) 7(NC2) 10(COMP_OUT) 12(REF) 13(VTAP)

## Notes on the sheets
sheet 10
- SHARED PAD
- SHARED PAD
sheet 12
- MECHANICAL PARTS
